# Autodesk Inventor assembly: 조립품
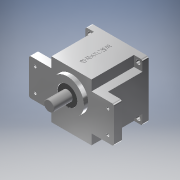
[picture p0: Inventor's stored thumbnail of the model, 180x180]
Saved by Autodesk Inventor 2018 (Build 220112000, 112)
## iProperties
Created: 2020-07
Part Number: 조립품
Material: 일반
Document SubType Name: Assembly
Designer: admin
Author: admin
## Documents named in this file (10)
- C:\Users\admin\Desktop\700707V1011\조립품.iam
- C:\Users\admin\Desktop\700707V1011\본체.ipt
- C:\Users\admin\Desktop\700707V1011\커버.ipt
- C:\Users\admin\Desktop\700707V1011\메인 축.ipt
- C:\Users\admin\Desktop\700707V1011\서브 축.ipt
- C:\Users\admin\Desktop\700707V1011\볼트 M4.ipt
- C:\Users\admin\Desktop\700707V1011\베어링 6003.ipt
- C:\Users\admin\Desktop\700707V1011\베어링 608.ipt
- C:\Users\admin\Desktop\700707V1011\오일 실 17 32 8.ipt
- C:\Users\admin\Desktop\700707V1011\오일 실 8 22 7.ipt
